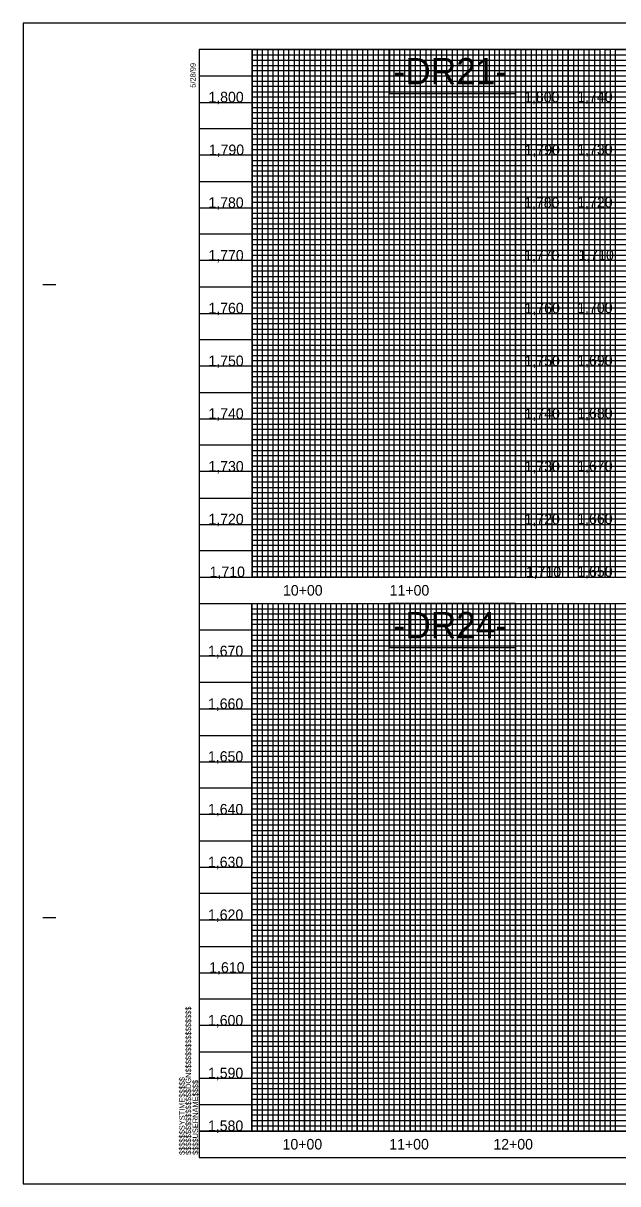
# Model space of a CAD drawing. Extents: x 505602 to 527661, y 418813 to 494436.
# Drawn here: x 505602 to 506166, y 483109 to 484209 of the extents above; entities that cross this region are included whole.
import ezdxf

# ---------------------------------------------------------------- set-up
doc = ezdxf.new("R2010")
doc.units = 0
for name, color, linetype in [('Exist Vertical Profile Vertical Axis Label', 7, 'Continuous'), ('Old_Level_1', 7, 'Continuous'), ('Prop Grid Mask', 7, 'Continuous'), ('Sheet Layout Profile Border Port 1', 7, 'Continuous'), ('Sheet Plot Border Outside CELL', 7, 'Continuous'), ('Sheet Profile CELL', 7, 'Continuous'), ('Sheet Profile Grid Major CELL', 7, 'Continuous'), ('Sheet Profile Grid Middle CELL', 7, 'Continuous'), ('Sheet Profile Grid Minor CELL', 7, 'Continuous')]:
    doc.layers.add(name, color=color, linetype=linetype)

msp = doc.modelspace()

# ---------------------------------------------------------------- linework, layer by layer
at = {"layer": 'Prop Grid Mask'}
for points in [[(506069.1, 484183.7), (505949.5, 484183.7), (505949.5, 484142), (506069.1, 484142)], [(506069.1, 483658.7), (505949.5, 483658.7), (505949.5, 483617), (506069.1, 483617)]]:
    msp.add_lwpolyline(points, close=True, dxfattribs=at)
at = {"layer": 'Sheet Layout Profile Border Port 1'}
for points in [[(505819.5, 484183.7), (506069.1, 484183.7), (506069.1, 483683.7), (505819.5, 483683.7)], [(505819.1, 483658.7), (506119.1, 483658.7), (506119.1, 483158.7), (505819.1, 483158.7)]]:
    msp.add_lwpolyline(points, close=True, dxfattribs=at)
at = {"layer": 'Sheet Plot Border Outside CELL'}
msp.add_lwpolyline([(505602.1, 483108.7), (507286.1, 483108.7), (507286.1, 484208.7), (505602.1, 484208.7)], close=True, dxfattribs=at)
at = {"layer": 'Sheet Profile CELL'}
for p, q in [((506119.1, 483683.7), (506119.1, 484183.7)), ((505620.6, 483961.2), (505633.1, 483961.2)), ((505769.1, 483683.7), (507269.1, 483683.7)), ((505769.1, 483658.7), (507269.1, 483658.7)), ((505620.6, 483361.2), (505633.1, 483361.2)), ((507269.1, 483158.7), (505769.1, 483158.7)), ((505769.1, 483133.7), (507269.1, 483133.7)), ((505769.1, 483133.7), (505769.1, 483133.7)), ((505769.1, 483133.7), (505769.1, 483133.7)), ((505769.1, 483133.7), (505769.1, 483133.7)), ((505769.1, 483133.7), (505769.1, 483133.7)), ((505769.1, 483133.7), (505769.1, 483133.7)), ((505769.1, 483133.7), (505769.1, 483133.7)), ((505769.1, 483133.7), (505769.1, 483133.7))]:
    msp.add_line(p, q, dxfattribs=at)
msp.add_lwpolyline([(507269.1, 484183.7), (505769.1, 484183.7), (505769.1, 483133.7), (507269.1, 483133.7)], close=True, dxfattribs=at)
msp.add_lwpolyline([(505806.6, 483133.7), (505806.6, 483133.7)], dxfattribs=at)
at = {"layer": 'Sheet Profile Grid Major CELL'}
for points in [[(505819.1, 484183.7), (505819.1, 483683.7), (505869.1, 483683.7), (505869.1, 484183.7), (505919.1, 484183.7), (505919.1, 483683.7), (505969.1, 483683.7), (505969.1, 484183.7), (506019.1, 484183.7), (506019.1, 483683.7), (506069.1, 483683.7), (506069.1, 484183.7), (506119.1, 484183.7), (506119.1, 483683.7), (506169.1, 483683.7)], [(505769.1, 484133.7), (507069.1, 484133.7)], [(507069.1, 484083.7), (505769.1, 484083.7), (505769.1, 484033.7), (507069.1, 484033.7)], [(507269.1, 483983.7), (505769.1, 483983.7), (505769.1, 483933.7), (507269.1, 483933.7)], [(507269.1, 483883.7), (505769.1, 483883.7), (505769.1, 483833.7), (507269.1, 483833.7)], [(507269.1, 483783.7), (505769.1, 483783.7), (505769.1, 483783.7), (505769.1, 483733.7), (507269.1, 483733.7)], [(505769.1, 483658.7), (505769.1, 483158.7), (505819.1, 483158.7), (505819.1, 483658.7), (505869.1, 483658.7), (505869.1, 483158.7), (505919.1, 483158.7), (505919.1, 483658.7), (505969.1, 483658.7), (505969.1, 483158.7), (506019.1, 483158.7), (506019.1, 483658.7), (506069.1, 483658.7), (506069.1, 483158.7), (506119.1, 483158.7), (506119.1, 483658.7), (506169.1, 483658.7)], [(505819.1, 483658.7), (505819.1, 483158.7), (505869.1, 483158.7), (505869.1, 483658.7), (505919.1, 483658.7), (505919.1, 483158.7), (505969.1, 483158.7), (505969.1, 483658.7), (506019.1, 483658.7), (506019.1, 483158.7), (506069.1, 483158.7), (506069.1, 483658.7), (506119.1, 483658.7), (506119.1, 483158.7), (506169.1, 483158.7)], [(507269.1, 483608.7), (505769.1, 483608.7)], [(507269.1, 483558.7), (505769.1, 483558.7), (505769.1, 483508.7), (507269.1, 483508.7)], [(507269.1, 483458.7), (505769.1, 483458.7), (505769.1, 483408.7), (507269.1, 483408.7)], [(507269.1, 483358.7), (505769.1, 483358.7), (505769.1, 483308.7), (507269.1, 483308.7)], [(507269.1, 483258.7), (505769.1, 483258.7), (505769.1, 483258.7), (505769.1, 483208.7), (507269.1, 483208.7)], [(507269.1, 483158.7), (505769.1, 483158.7)]]:
    msp.add_lwpolyline(points, dxfattribs=at)
at = {"layer": 'Sheet Profile Grid Middle CELL'}
msp.add_line((505769.1, 484158.7), (507069, 484158.7), dxfattribs=at)
msp.add_line((505769.1, 484158.7), (507069, 484158.7), dxfattribs=at)
for points in [[(505844.1, 484183.7), (505844.1, 483683.7), (505894.1, 483683.7), (505894.1, 484183.7), (505944.1, 484183.7), (505944.1, 483683.7), (505994.1, 483683.7), (505994.1, 484183.7), (506044.1, 484183.7), (506044.1, 483683.7), (506094.1, 483683.7), (506094.1, 484183.7), (506144.1, 484183.7), (506144.1, 483683.7), (506194.1, 483683.7)], [(507069.1, 484108.7), (505769.1, 484108.7), (505769.1, 484058.7), (507069.1, 484058.7)], [(507269.1, 484008.7), (505769.1, 484008.7), (505769.1, 483958.7), (507094.1, 483958.7)], [(507269.1, 483908.7), (505769.1, 483908.7), (505769.1, 483858.7), (507269.1, 483858.7)], [(507269.1, 483808.7), (505769.1, 483808.7), (505769.1, 483758.7), (507269.1, 483758.7)], [(507269.1, 483708.7), (505769.1, 483708.7)], [(505794.1, 483658.7), (505844.1, 483658.7), (505844.1, 483158.7), (505894.1, 483158.7), (505894.1, 483658.7), (505944.1, 483658.7), (505944.1, 483158.7), (505994.1, 483158.7), (505994.1, 483658.7), (506044.1, 483658.7), (506044.1, 483158.7), (506094.1, 483158.7), (506094.1, 483658.7), (506144.1, 483658.7), (506144.1, 483158.7), (506194.1, 483158.7)], [(505769.1, 483633.7), (507269.1, 483633.7)], [(507269.1, 483583.7), (505769.1, 483583.7), (505769.1, 483533.7), (507269.1, 483533.7)], [(507269.1, 483483.7), (505769.1, 483483.7), (505769.1, 483433.7), (507269.1, 483433.7)], [(507269.1, 483383.7), (505769.1, 483383.7), (505769.1, 483333.7), (507269.1, 483333.7)], [(507269.1, 483283.7), (505769.1, 483283.7), (505769.1, 483233.7), (507269.1, 483233.7)], [(507269.1, 483183.7), (505769.1, 483183.7)]]:
    msp.add_lwpolyline(points, dxfattribs=at)
at = {"layer": 'Sheet Profile Grid Minor CELL'}
for p, q in [((505819.1, 484178.7), (507069.1, 484178.7)), ((505819.1, 484173.7), (505819.1, 484173.7)), ((507069.1, 484173.7), (505819.1, 484173.4)), ((505819.1, 484168.7), (507069.1, 484168.7)), ((507069, 484048.7), (505819.1, 484048.7)), ((507069.1, 484043.7), (505819.1, 484043.7)), ((507069.1, 484038.7), (505819.1, 484038.7)), ((505819.1, 484028.7), (507069.1, 484028.7)), ((507069.1, 484023.7), (505819.1, 484023.7)), ((505819.1, 484018.7), (507219.1, 484018.7)), ((507219.1, 483998.7), (505819.1, 483998.7)), ((505819.1, 483993.7), (507219.1, 483993.7)), ((507219.1, 483973.7), (505819.1, 483973.7)), ((505819.1, 483968.7), (507219.1, 483968.7)), ((507219.1, 483948.7), (505819.1, 483948.7)), ((505819.1, 483943.7), (507219.1, 483943.7)), ((507219.1, 483938.7), (505819.1, 483938.7)), ((505819.1, 483928.7), (507219.1, 483928.7)), ((507219.1, 483923.7), (505819.1, 483923.7)), ((505819.1, 483918.7), (507219.1, 483918.7)), ((507219.1, 483913.7), (505819.1, 483913.7)), ((505819.1, 483903.7), (507219.1, 483903.7)), ((507219.1, 483898.7), (505819.1, 483898.7)), ((505819.1, 483893.7), (507219.1, 483893.7)), ((507219.1, 483888.7), (505819.1, 483888.7)), ((505819.1, 483878.7), (507219.1, 483878.7)), ((507219.1, 483873.7), (505819.1, 483873.7)), ((505819.1, 483868.7), (507219.1, 483868.7)), ((507219.1, 483863.7), (505819.1, 483863.7)), ((505819.1, 483853.7), (507219.1, 483853.7)), ((507219.1, 483848.7), (505819.1, 483848.7)), ((505819.1, 483843.7), (507219.1, 483843.7)), ((507219.1, 483838.7), (505819.1, 483838.7)), ((505819.1, 483828.7), (507219.1, 483828.7)), ((507219.1, 483823.7), (505819.1, 483823.7)), ((505819.1, 483818.7), (507219.1, 483818.7)), ((507219.1, 483813.7), (505819.1, 483813.7)), ((505819.1, 483803.7), (507219.1, 483803.7)), ((507219.1, 483798.7), (505819.1, 483798.7)), ((507219.1, 483793.7), (505819.1, 483793.7)), ((507219.1, 483788.7), (505819.1, 483788.7)), ((505819.1, 483778.7), (507219.1, 483778.7)), ((507219.1, 483773.7), (505819.1, 483773.7)), ((505819.1, 483768.7), (507219.1, 483768.7)), ((507219.1, 483763.7), (505819.1, 483763.7)), ((505819.1, 483753.7), (507219.1, 483753.7)), ((507219.1, 483748.7), (505819.1, 483748.7)), ((505819.1, 483743.7), (507219.1, 483743.7)), ((507219.1, 483738.7), (505819.1, 483738.7)), ((505819.1, 483728.7), (507219.1, 483728.7)), ((507219.1, 483723.7), (505819.1, 483723.7)), ((505819.1, 483718.7), (507219.1, 483718.7)), ((507219.1, 483713.7), (505819.1, 483713.7)), ((505819.1, 483703.7), (507219.1, 483703.7)), ((507219.1, 483698.7), (505819.1, 483698.7)), ((505819.1, 483693.7), (507219.1, 483693.7)), ((505819.1, 483653.7), (507219.1, 483653.7)), ((507219.1, 483648.7), (505819.1, 483648.7)), ((505819.1, 483643.7), (507219.1, 483643.7)), ((507219.1, 483638.7), (505819.1, 483638.7)), ((505819.1, 483628.7), (507219.1, 483628.7)), ((507219.1, 483623.7), (505819.1, 483623.7)), ((505819.1, 483618.7), (507219.1, 483618.7)), ((507219.1, 483613.7), (505819.1, 483613.7)), ((505819.1, 483603.7), (507219.1, 483603.7)), ((507219.1, 483598.7), (505819.1, 483598.7)), ((505819.1, 483593.7), (507219.1, 483593.7)), ((507219.1, 483588.7), (505819.1, 483588.7)), ((505819.1, 483578.7), (507219.1, 483578.7)), ((507219.1, 483573.7), (505819.1, 483573.7)), ((505819.1, 483568.7), (507219.1, 483568.7)), ((507219.1, 483563.7), (505819.1, 483563.7)), ((505819.1, 483553.7), (507219.1, 483553.7)), ((507219.1, 483548.7), (505819.1, 483548.7)), ((505819.1, 483543.7), (507219.1, 483543.7)), ((507219.1, 483538.7), (505819.1, 483538.7)), ((505819.1, 483528.7), (507219.1, 483528.7)), ((507219.1, 483523.7), (505819.1, 483523.7)), ((505819.1, 483518.7), (507219.1, 483518.7)), ((507219.1, 483513.7), (505819.1, 483513.7)), ((505819.1, 483503.7), (507219.1, 483503.7)), ((507219.1, 483498.7), (505819.1, 483498.7)), ((505819.1, 483493.7), (507219.1, 483493.7)), ((507219.1, 483488.7), (505819.1, 483488.7)), ((505819.1, 483478.7), (507219.1, 483478.7)), ((507219.1, 483473.7), (505819.1, 483473.7)), ((505819.1, 483468.7), (507219.1, 483468.7)), ((507219.1, 483463.7), (505819.1, 483463.9)), ((505819.1, 483453.7), (507219.1, 483453.7)), ((507219.1, 483448.7), (505819.1, 483448.7)), ((505819.1, 483443.7), (507219.1, 483443.7)), ((507219.1, 483438.7), (505819.1, 483438.7)), ((505819.1, 483428.7), (507219.1, 483428.7)), ((507219.1, 483423.7), (505819.1, 483423.7)), ((505819.1, 483418.7), (507219.1, 483418.7)), ((507219.1, 483413.7), (505819.1, 483413.7)), ((505819.1, 483403.7), (507219.1, 483403.7)), ((507219.1, 483398.7), (505819.1, 483398.7)), ((505819.1, 483393.7), (507219.1, 483393.7)), ((507219.1, 483388.7), (505819.1, 483388.7)), ((505819.1, 483378.7), (507219.1, 483378.7)), ((507219.1, 483373.7), (505819.1, 483373.7)), ((505819.1, 483368.7), (507219.1, 483368.7)), ((507219.1, 483363.7), (505819.1, 483363.7)), ((505819.1, 483353.7), (507219.1, 483353.7)), ((507219.1, 483348.7), (505819.1, 483348.7)), ((505819.1, 483343.7), (507219.1, 483343.7)), ((507219.1, 483338.7), (505819.1, 483338.7)), ((505819.1, 483328.7), (507219.1, 483328.7)), ((507219.1, 483323.7), (505819.1, 483323.7)), ((505819.1, 483318.7), (507219.1, 483318.7)), ((507219.1, 483313.7), (505819.1, 483313.7)), ((505819.1, 483303.7), (507219.1, 483303.7)), ((507219.1, 483298.7), (505819.1, 483298.7)), ((505819.1, 483293.7), (507219.1, 483293.7)), ((507219.1, 483288.7), (505819.1, 483288.7)), ((505819.1, 483278.7), (507219.1, 483278.7)), ((507219.1, 483273.7), (505819.1, 483273.7)), ((505819.1, 483268.7), (507219.1, 483268.7)), ((507219.1, 483263.7), (505819.1, 483263.7)), ((505819.1, 483253.7), (507219.1, 483253.7)), ((507219.1, 483248.7), (505819.1, 483248.7)), ((505819.1, 483243.7), (507219.1, 483243.7)), ((507219.1, 483238.7), (505819.1, 483238.7)), ((505819.1, 483228.7), (507219.1, 483228.7)), ((507219.1, 483223.7), (505819.1, 483223.7)), ((505819.1, 483218.7), (507219.1, 483218.7)), ((507219.1, 483213.7), (505819.1, 483213.7)), ((505819.1, 483203.7), (507219.1, 483203.7)), ((507219.1, 483198.7), (505819.1, 483198.7)), ((505819.1, 483193.7), (507219.1, 483193.7)), ((507219.1, 483188.7), (505819.1, 483188.7)), ((505819.1, 483178.7), (507219.1, 483178.7)), ((507219.1, 483173.7), (505819.1, 483173.7)), ((505819.1, 483168.7), (507219.1, 483168.7)), ((505819.1, 483163.7), (507219.1, 483163.7))]:
    msp.add_line(p, q, dxfattribs=at)
for points in [[(505824.1, 484183.7), (505824.1, 483683.7), (505829.1, 483683.7), (505829.1, 484183.7), (505834.1, 484183.7), (505834.1, 483683.7), (505839.1, 483683.7), (505839.1, 484183.7), (505849.1, 484183.7), (505849.1, 483683.7), (505854.1, 483683.7), (505854.1, 484183.7), (505859.1, 484183.7), (505859.1, 483683.7), (505864.1, 483683.7), (505874.1, 483683.7), (505879.1, 483683.7), (505879.1, 484183.7), (505884.1, 484183.7), (505884.1, 483683.7), (505889.1, 483683.7), (505889.1, 484183.7), (505899.1, 484183.7), (505899.1, 483683.7), (505904.1, 483683.7), (505904.1, 484183.7), (505909.1, 484183.7), (505909.1, 483683.7), (505914.1, 483683.7), (505914.1, 484183.7), (505924.1, 484183.7), (505924.1, 483683.7), (505929.1, 483683.7), (505929.1, 484183.7), (505934.1, 484183.7), (505934.1, 483683.7), (505939.1, 483683.7), (505939.1, 484183.7), (505949.1, 484183.7), (505949.1, 483683.7), (505954.1, 483683.7), (505954.1, 484183.7), (505959.1, 484183.7), (505959.1, 483683.7), (505964.1, 483683.7), (505964.1, 484183.7), (505974.1, 484183.7), (505974.1, 483683.7), (505979.1, 483683.7), (505979.1, 484183.7), (505984.1, 484183.7), (505984.1, 483683.7), (505989.1, 483683.7), (505989.1, 484183.7), (505999.1, 484183.7), (505999.1, 483683.7), (506004.1, 483683.7), (506004.1, 484183.7), (506009.1, 484183.7), (506009.1, 483683.7), (506014.1, 483683.7), (506014.1, 484183.7), (506024.1, 484183.7), (506024.1, 483683.7), (506029.1, 483683.7), (506029.1, 484183.7), (506034.1, 484183.7), (506034.1, 483683.7)], [(505864.1, 483683.7), (505864.1, 484183.7), (505874.1, 484183.7), (505874.1, 483683.7)], [(506034.1, 483683.7), (506039.1, 483683.7), (506039.1, 484183.7), (506049.1, 484183.7), (506049.1, 483683.7), (506054.1, 483683.7), (506054.1, 484183.7), (506059.1, 484183.7), (506059.1, 483683.7), (506064.1, 483683.7), (506064.1, 484183.7), (506074.1, 484183.7), (506074.1, 483683.7), (506079.1, 483683.7), (506079.1, 484183.7), (506084.1, 484183.7), (506084.1, 483683.7), (506089.1, 483683.7), (506089.1, 484183.7), (506099.1, 484183.7), (506099.1, 483683.7), (506104.1, 483683.7), (506104.1, 484183.7), (506109.1, 484183.7), (506109.1, 483683.7), (506114.1, 483683.7), (506114.1, 484183.7), (506124.1, 484183.7), (506124.1, 483683.7), (506129.1, 483683.7), (506129.1, 484183.7), (506134.1, 484183.7), (506134.1, 483683.7), (506139.1, 483683.7), (506139.1, 484183.7), (506149.1, 484183.7), (506149.1, 483683.7), (506154.1, 483683.7), (506154.1, 484183.7), (506159.1, 484183.7), (506159.1, 483683.7), (506164.1, 483683.7), (506164.1, 484183.7), (506174.1, 484183.7)], [(507069.1, 484163.7), (505819.1, 484163.7), (505819.1, 484153.7), (507069.1, 484153.7)], [(507069, 484148.7), (505819.1, 484148.7), (505819.1, 484143.7), (507069.1, 484143.7)], [(507069.1, 484138.7), (505819.1, 484138.7), (505819.1, 484128.7), (507069.1, 484128.7)], [(507069.1, 484123.7), (505819.1, 484123.7), (505819.1, 484118.7), (507069.1, 484118.7)], [(507069.1, 484113.7), (505819.1, 484113.7), (505819.1, 484103.7), (507069.1, 484103.7)], [(507069.1, 484098.7), (505819.1, 484098.7), (505819.1, 484093.7), (507069.1, 484093.7)], [(507069.1, 484088.7), (505819.1, 484088.7), (505819.1, 484078.7), (507069.1, 484078.7)], [(507069.1, 484073.6), (505819.2, 484073.6), (505819.2, 484068.7), (507069.1, 484068.7)], [(507069.1, 484063.7), (505819.1, 484063.7), (505819.1, 484053.7), (507069.1, 484053.7)], [(507219.1, 484013.7), (505819.1, 484013.7), (505819.1, 484003.7), (507219.1, 484003.7)], [(507219.1, 483988.7), (505819.1, 483988.7), (505819.1, 483978.7), (507219.1, 483978.7)], [(507219.1, 483963.7), (505819.1, 483963.7), (505819.1, 483953.7), (507219.1, 483953.7)], [(507219.1, 483688.7), (505819.1, 483688.7)], [(505819.1, 483658.7), (505824.1, 483658.7), (505824.1, 483158.7), (505829.1, 483158.7), (505829.1, 483658.7), (505834.1, 483658.7), (505834.1, 483158.7), (505839.1, 483158.7), (505839.1, 483658.7), (505849.1, 483658.7), (505849.1, 483158.7), (505854.1, 483158.7), (505854.1, 483658.7), (505859.1, 483658.7), (505859.1, 483158.7), (505864.1, 483158.7), (505874.1, 483158.7), (505879.1, 483158.7), (505879.1, 483658.7), (505884.1, 483658.7), (505884.1, 483158.7), (505889.1, 483158.7), (505889.1, 483658.7), (505899.1, 483658.7), (505899.1, 483158.7), (505904.1, 483158.7), (505904.1, 483658.7), (505909.1, 483658.7), (505909.1, 483158.7), (505914.1, 483158.7), (505914.1, 483658.7), (505924.1, 483658.7), (505924.1, 483158.7), (505929.1, 483158.7), (505929.1, 483658.7), (505934.1, 483658.7), (505934.1, 483158.7), (505939.1, 483158.7), (505939.1, 483658.7), (505949.1, 483658.7), (505949.1, 483158.7), (505954.1, 483158.7), (505954.1, 483658.7), (505959.1, 483658.7), (505959.1, 483158.7), (505964.1, 483158.7), (505964.1, 483658.7), (505974.1, 483658.7), (505974.1, 483158.7), (505979.1, 483158.7), (505979.1, 483658.7), (505984.1, 483658.7), (505984.1, 483158.7), (505989.1, 483158.7), (505989.1, 483658.7), (505999.1, 483658.7), (505999.1, 483158.7), (506004.1, 483158.7), (506004.1, 483658.7), (506009.1, 483658.7), (506009.1, 483158.7), (506014.1, 483158.7), (506014.1, 483658.7), (506024.1, 483658.7), (506024.1, 483158.7), (506029.1, 483158.7), (506029.1, 483658.7), (506034.1, 483658.7), (506034.1, 483158.7)], [(505864.1, 483158.7), (505864.1, 483658.7), (505874.1, 483658.7), (505874.1, 483158.7)], [(506034.1, 483158.7), (506039.1, 483158.7), (506039.1, 483658.7), (506049.1, 483658.7), (506049.1, 483158.7), (506054.1, 483158.7), (506054.1, 483658.7), (506059.1, 483658.7), (506059.1, 483158.7), (506064.1, 483158.7), (506064.1, 483658.7), (506074.1, 483658.7), (506074.1, 483158.7), (506079.1, 483158.7), (506079.1, 483658.7), (506084.1, 483658.7), (506084.1, 483158.7), (506089.1, 483158.7), (506089.1, 483658.7), (506099.1, 483658.7), (506099.1, 483158.7), (506104.1, 483158.7), (506104.1, 483658.7), (506109.1, 483658.7), (506109.1, 483158.7), (506114.1, 483158.7), (506114.1, 483658.7), (506124.1, 483658.7), (506124.1, 483158.7), (506129.1, 483158.7), (506129.1, 483658.7), (506134.1, 483658.7), (506134.1, 483158.7), (506139.1, 483158.7), (506139.1, 483658.7), (506149.1, 483658.7), (506149.1, 483158.7), (506154.1, 483158.7), (506154.1, 483658.7), (506159.1, 483658.7), (506159.1, 483158.7), (506164.1, 483158.7), (506164.1, 483658.7), (506174.1, 483658.7)]]:
    msp.add_lwpolyline(points, dxfattribs=at)

# ---------------------------------------------------------------- texts
at = {"layer": 'Exist Vertical Profile Vertical Axis Label'}
for s, p in [('1,800', (505777.8, 484133.7)), ('1,800', (506077.4, 484133.7)), ('1,740', (506127.8, 484134)), ('1,790', (505778.2, 484083.7)), ('1,790', (506077.8, 484083.7)), ('1,730', (506127.8, 484084)), ('1,720', (506127.8, 484034)), ('1,780', (505777.8, 484033.7)), ('1,780', (506077.4, 484033.7)), ('1,770', (505777.8, 483983.7)), ('1,770', (506077.4, 483983.7)), ('1,710', (506129, 483984)), ('1,760', (505777.8, 483933.7)), ('1,760', (506077.8, 483933.7)), ('1,700', (506127.8, 483934)), ('1,750', (505777.8, 483883.7)), ('1,750', (506077.8, 483883.7)), ('1,690', (506127.8, 483884)), ('1,740', (505777.8, 483833.7)), ('1,740', (506077.8, 483833.7)), ('1,680', (506127.8, 483834)), ('1,730', (505777.8, 483783.7)), ('1,730', (506077.8, 483783.7)), ('1,670', (506127.8, 483784)), ('1,720', (505777.8, 483733.7)), ('1,720', (506077.8, 483733.7)), ('1,660', (506127.8, 483734)), ('1,710', (505779, 483683.7)), ('1,710', (506079, 483683.7)), ('1,650', (506127.8, 483684)), ('10+00', (505848.6, 483666.2)), ('11+00', (505949.8, 483666.2)), ('1,670', (505777.4, 483608.7)), ('1,660', (505777.4, 483558.7)), ('1,650', (505777.4, 483508.7)), ('1,640', (505777.4, 483458.7)), ('1,630', (505777.4, 483408.7)), ('1,620', (505777.4, 483358.7)), ('1,610', (505778.6, 483308.7)), ('1,600', (505777.4, 483258.7)), ('1,590', (505777.4, 483208.7)), ('1,580', (505777.4, 483158.7)), ('10+00', (505848.2, 483141.2)), ('11+00', (505949.4, 483141.2)), ('12+00', (506048.2, 483141.2))]:
    msp.add_text(s, height=10, dxfattribs=at).set_placement(p)
at = {"layer": 'Old_Level_1'}
for s, p in [('-DR21-', (505953.5, 484150.7)), ('-DR24-', (505953.5, 483625.7))]:
    msp.add_text(s, height=25, dxfattribs=at).set_placement(p)
at = {"layer": 'Sheet Profile CELL'}
for s, p in [('5/28/99', (505765.8, 484147.6)), ('$$$$$$$$$$$$$$$$DGN$$$$$$$$$$$$$$$$', (505761.4, 483136.1)), ('$$$$$$SYSTIME$$$$$', (505755.4, 483136.1)), ('$$$$USERNAME$$$$', (505768, 483136.1))]:
    msp.add_text(s, height=5.25, rotation=90, dxfattribs=at).set_placement(p)

doc.saveas('drawing.dxf')
